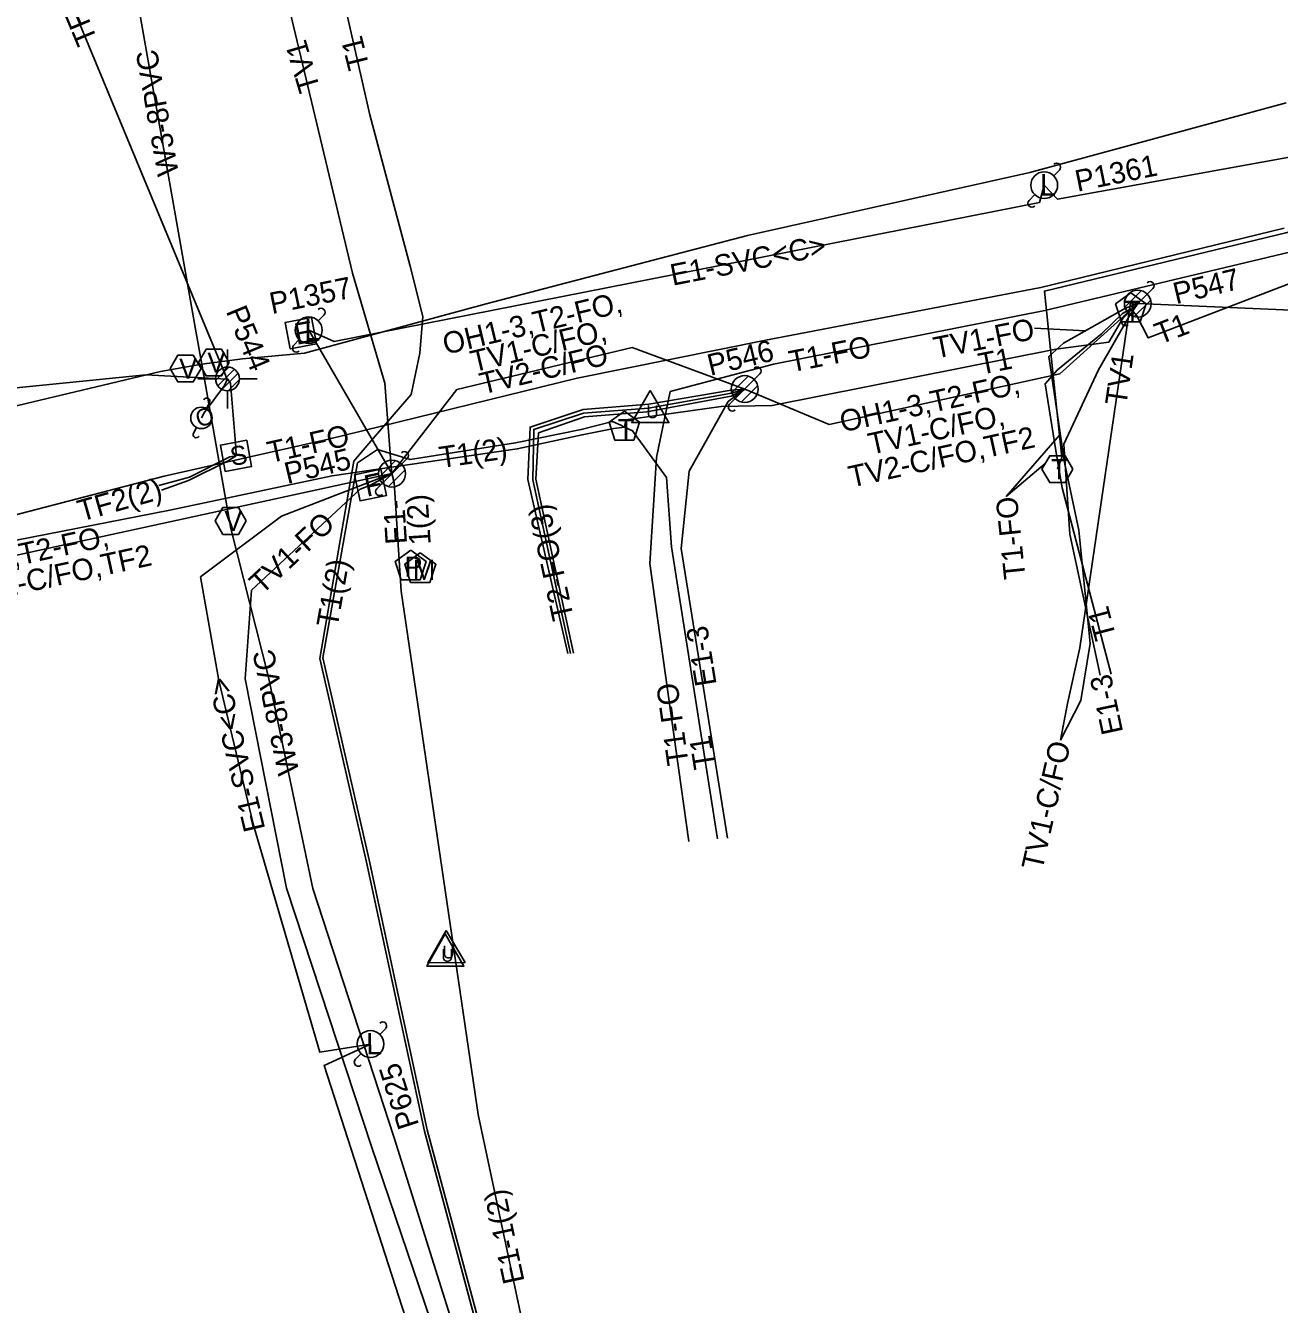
# Model space of a CAD drawing. Extents: x 2336688 to 2352634, y 362473 to 369571.
# Drawn here: x 2348017.1 to 2348250.9, y 367300.5 to 367539 of the extents above; entities that cross this region are included whole.
import ezdxf

# ---------------------------------------------------------------- set-up
doc = ezdxf.new("R2010")
doc.units = 0
for name, color, linetype in [('RD_EX_DV_Prop', 7, 'Continuous'), ('RD_EX_DV_TX_Prop', 7, 'Continuous'), ('RD_EX_RW', 7, 'Continuous'), ('RD_EX_RW_TX', 7, 'Continuous'), ('RD_HC_Data_Tic', 7, 'Continuous'), ('RD_PD_CstnLmt', 7, 'Continuous'), ('RD_PD_Final_TrvlWay', 7, 'Continuous'), ('RD_PD_FOC', 7, 'Continuous'), ('RD_PD_PatLn3', 7, 'Continuous'), ('RD_PD_PatLn4', 7, 'Continuous'), ('RD_SHT_ShtClip', 7, 'Continuous'), ('RD_Sketch2', 7, 'Continuous'), ('RD_Sketch8', 7, 'Continuous')]:
    doc.layers.add(name, color=color, linetype=linetype)

msp = doc.modelspace()

# ---------------------------------------------------------------- linework, layer by layer
at = {"layer": 'RD_EX_RW'}
for p, q in [((2348205.22, 367482.58), (2348214.7, 367482.09)), ((2348199.96, 367451.19), (2348209.88, 367462.6)), ((2348199.96, 367451.19), (2348207.23, 367457.35)), ((2348210.09, 367405.73), (2348213.89, 367413.12)), ((2348210.09, 367405.73), (2348211.36, 367412.58))]:
    msp.add_line(p, q, dxfattribs=at)
at = {"layer": 'RD_EX_RW_TX'}
for points in [[(2348085.42, 367455.46), (2348085.25, 367456.81), (2348084.11, 367472.36), (2348078.05, 367492.84), (2348059.44, 367571.03), (2348057.43, 367578.05), (2348054.24, 367593.15), (2348053.27, 367598.58), (2348079.95, 367605.18), (2348132.88, 367615.72), (2348177.98, 367626.63), (2348230.33, 367640.4), (2348274.48, 367651.48), (2348294.14, 367658.1), (2348322.12, 367668.38), (2348370.04, 367683.85), (2348388.49, 367688.84), (2348418.25, 367692.63), (2348451.32, 367697.47), (2348453.28, 367700.17), (2348444.65, 367725.62), (2348423.89, 367760.2), (2348406.22, 367798.41), (2348404.33, 367800.52)], [(2348277.67, 367644.22), (2348227.84, 367633.58), (2348178.94, 367621.43), (2348133.69, 367610.27), (2348080.57, 367598.27), (2348068.66, 367596.86), (2348066.5, 367591.91), (2348067.19, 367583.21), (2348069.73, 367573.23), (2348081.3, 367522.36), (2348088.83, 367494.16)], [(2348209.5, 367456.28), (2348210.32, 367458.48), (2348208.63, 367474.37), (2348207.08, 367489.5), (2348252.08, 367500.34), (2348310.01, 367516.64), (2348348.6, 367526.57), (2348355.1, 367525.87), (2348359.53, 367524.74)], [(2348359.53, 367524.74), (2348355.51, 367524.43), (2348310.45, 367513.44), (2348252.78, 367496.75), (2348207.14, 367485.87), (2348156.56, 367475.89), (2348137.31, 367470.75), (2348134.76, 367458.49), (2348133.52, 367438.68), (2348140.76, 367386.86)], [(2347470.17, 367338.02), (2347527.74, 367350.46), (2347547.36, 367354.41), (2347551.42, 367355.46), (2347554.94, 367356.11), (2347601.32, 367363.67), (2347672.79, 367378.26), (2347716.22, 367388.49), (2347732.21, 367393.25), (2347737, 367394.55), (2347740.32, 367395.23), (2347763.96, 367400.82), (2347812.85, 367411.94), (2347861.88, 367418.78), (2347886.02, 367419.64), (2347912.08, 367422.89), (2347964.53, 367437), (2348014.8, 367447.66), (2348042.92, 367455.01), (2348073.57, 367461.89), (2348119.92, 367473.29), (2348155.43, 367480.43), (2348206.38, 367490.17), (2348251.79, 367501.21)], [(2348088.83, 367494.16), (2348091.17, 367484.78), (2348090.64, 367477.91), (2348089.01, 367470.2), (2348081.09, 367461.1), (2348078.33, 367457.81), (2348071.94, 367420.99), (2348080.69, 367382.96), (2348091.47, 367332.8), (2348104.03, 367285.99), (2348117.2, 367236.51), (2348130.94, 367187.87), (2348140.57, 367137.57), (2348151.22, 367087.99), (2348162.48, 367041.93), (2348170.87, 366987.09)], [(2348253.93, 367491.37), (2348226.44, 367480.77), (2348224.32, 367484.9), (2348223.18, 367486.18), (2348222.03, 367484.96), (2348219.07, 367479.97), (2348209.19, 367478.65), (2348156.33, 367468.19), (2348146.8, 367468), (2348129.01, 367465.51), (2348128.75, 367464.11), (2348126.77, 367463.88), (2348120.88, 367462.71), (2348108.79, 367460.06), (2348074.24, 367455.07), (2348044, 367448.64), (2348015.43, 367443.03)], [(2348213.89, 367413.12), (2348215.59, 367423.8), (2348213.46, 367444.88), (2348210.82, 367457.54), (2348207.89, 367477.33), (2348210.65, 367479.79), (2348222.17, 367486.34), (2348224.48, 367487.16)], [(2348224.48, 367487.16), (2348223.14, 367487.36), (2348213.69, 367422.97), (2348211.36, 367412.58)], [(2348219.54, 367418.03), (2348210.35, 367452.79), (2348209.46, 367458.22), (2348207.2, 367472.18), (2348209.53, 367474.84), (2348217.73, 367481.54), (2348221.6, 367485.34), (2348223.18, 367486.18)], [(2348118.22, 367421.93), (2348110.77, 367454.36), (2348111.16, 367464.14), (2348121.09, 367467.44), (2348133.34, 367468.43), (2348148.66, 367471.02), (2348151.19, 367471.23)], [(2348118.73, 367421.93), (2348111.71, 367454.32), (2348111.86, 367463.71), (2348121.15, 367466.74), (2348133.25, 367467.67), (2348148.75, 367470.45), (2348151.19, 367471.23)], [(2348119.26, 367421.96), (2348112.25, 367454.45), (2348112.74, 367463.04), (2348121.33, 367466.07), (2348132.96, 367466.99), (2348148.69, 367469.92), (2348151.19, 367471.23)], [(2348171.52, 366987.34), (2348163.05, 367042.11), (2348151.67, 367087.97), (2348141.26, 367137.73), (2348131.53, 367187.73), (2348117.77, 367236.66), (2348104.66, 367285.95), (2348091.99, 367333.07), (2348081.16, 367383.42), (2348072.54, 367421.09), (2348078.97, 367457.45), (2348082.71, 367459.94), (2348088.78, 367458.12), (2348108.47, 367461.17), (2348120.71, 367463.68), (2348126.54, 367465.18), (2348128.12, 367464.52), (2348128.75, 367464.11), (2348130.27, 367463.44), (2348136.63, 367454.72), (2348137.56, 367441.82), (2348146.14, 367387.35)], [(2348085.42, 367455.46), (2348081.41, 367453.31), (2348079.48, 367452.55), (2348059.25, 367433.73), (2348058.03, 367417.18), (2348065.76, 367378.12), (2348081.58, 367329.95), (2348097.08, 367284.38), (2348111.65, 367235.56), (2348125.36, 367187.13), (2348134.58, 367138.22), (2348143.49, 367087.34), (2348150.94, 367037.73), (2348156.27, 366986.52)]]:
    msp.add_lwpolyline(points, dxfattribs=at)
for points in [[(2348223.18, 367489.18), (2348220.33, 367487.1), (2348221.42, 367483.75), (2348224.95, 367483.75), (2348226.04, 367487.1)], [(2348128.75, 367467.11), (2348125.9, 367465.04), (2348126.99, 367461.68), (2348130.51, 367461.68), (2348131.6, 367465.04)], [(2348212.39, 367456.28), (2348210.94, 367458.78), (2348208.06, 367458.78), (2348206.61, 367456.28), (2348208.06, 367453.78), (2348210.94, 367453.78)], [(2348083.36, 367456.26), (2348078.46, 367455.25), (2348079.47, 367450.35), (2348084.37, 367451.37)]]:
    msp.add_lwpolyline(points, close=True, dxfattribs=at)
at = {"layer": 'RD_HC_Data_Tic'}
for p, q in [((2348208.8, 367511.02), (2348209.86, 367512.09)), ((2348204.2, 367506.43), (2348205.26, 367507.49)), ((2348225.13, 367489.58), (2348222.07, 367486.52)), ((2348227.31, 367489.99), (2348226.25, 367488.93)), ((2348226.25, 367488.93), (2348222.71, 367485.4)), ((2348226.89, 367487.81), (2348223.83, 367484.75)), ((2348071.67, 367483.98), (2348072.73, 367485.04)), ((2348222.71, 367485.4), (2348221.65, 367484.34)), ((2348067.08, 367479.38), (2348068.14, 367480.45)), ((2348054.74, 367475.33), (2348054.74, 367478.62)), ((2348055.03, 367475.31), (2348052.54, 367472.82)), ((2348052.52, 367473.11), (2348049.21, 367473.11)), ((2348056.04, 367474.91), (2348052.95, 367471.81)), ((2348056.7, 367474.15), (2348053.7, 367471.15)), ((2348056.95, 367472.98), (2348054.87, 367470.9)), ((2348060.26, 367473.12), (2348056.95, 367473.12)), ((2348151.84, 367473.64), (2348148.78, 367470.58)), ((2348152.96, 367473), (2348149.42, 367469.46)), ((2348154.02, 367474.06), (2348152.96, 367473)), ((2348054.74, 367467.62), (2348054.74, 367470.9)), ((2348153.61, 367471.88), (2348150.54, 367468.81)), ((2348050.84, 367467.62), (2348051.4, 367468.68)), ((2348149.42, 367469.46), (2348148.36, 367468.4)), ((2348048.39, 367463.03), (2348048.95, 367464.09)), ((2348088.25, 367458.29), (2348087.19, 367457.23)), ((2348086.07, 367457.88), (2348083.01, 367454.81)), ((2348087.19, 367457.23), (2348083.65, 367453.69)), ((2348087.84, 367456.11), (2348084.77, 367453.05)), ((2348083.65, 367453.69), (2348082.59, 367452.63)), ((2348083.16, 367350.85), (2348084.2, 367351.92)), ((2348078.61, 367346.21), (2348079.66, 367347.28))]:
    msp.add_line(p, q, dxfattribs=at)
for centre, radius in [((2348207.03, 367509.26), 2.5), ((2348224.48, 367487.16), 2.5), ((2348069.9, 367482.21), 2.5), ((2348054.74, 367473.12), 2.22), ((2348151.19, 367471.23), 2.5), ((2348049.9, 367465.86), 2), ((2348085.42, 367455.46), 2.5), ((2348081.41, 367349.06), 2.5)]:
    msp.add_circle(centre, radius, dxfattribs=at)
for centre, radius, start, end in [((2348209.33, 367512.62), 0.75, 315, 135), ((2348204.73, 367505.9), 0.75, 135, 315), ((2348226.78, 367490.52), 0.75, 315, 135), ((2348072.2, 367485.57), 0.75, 315, 135), ((2348222.18, 367483.81), 0.75, 135, 315), ((2348067.61, 367478.85), 0.75, 135, 315), ((2348153.49, 367474.59), 0.75, 315, 135), ((2348050.87, 367468.96), 0.6, 331.9175, 151.9175), ((2348148.89, 367467.87), 0.75, 135, 315), ((2348048.92, 367462.75), 0.6, 151.9175, 331.9175), ((2348087.72, 367458.82), 0.75, 315, 135), ((2348083.12, 367452.1), 0.75, 135, 315), ((2348083.67, 367352.45), 0.75, 315.5955, 135.5955), ((2348079.14, 367345.68), 0.75, 135.5955, 315.5955)]:
    msp.add_arc(centre, radius, start, end, dxfattribs=at)
at = {"layer": 'RD_PD_Final_TrvlWay'}
for points in [[(2348085.42, 367455.46), (2348069.9, 367482.21), (2348074.61, 367480.08), (2348206.15, 367506.02), (2348207.03, 367509.26), (2348209.48, 367506.65), (2348332.4, 367528.92), (2348335.73, 367532.57)], [(2348217.45, 367417.88), (2348211.82, 367444.18), (2348210.7, 367460.98), (2348217.13, 367474.8), (2348222.98, 367485.03), (2348224.48, 367487.16)], [(2348151.19, 367471.23), (2348148.08, 367468.9), (2348140.85, 367455.9), (2348139.33, 367441.46), (2348147.98, 367387.45)], [(2348085.42, 367455.46), (2348064.82, 367447.53), (2348049.72, 367436.2), (2348053.15, 367416.84), (2348059.59, 367389.88), (2348071.96, 367347.56), (2348081.41, 367349.06), (2348072.77, 367345.05), (2348105.67, 367243.13), (2348112.74, 367243.38), (2348106.57, 367240.06), (2348121.26, 367184.97), (2348129.69, 367138.16), (2348138.15, 367139.68), (2348141, 367139.48), (2348138.4, 367138.3), (2348129.94, 367136.78), (2348147.57, 367038.81), (2348157.07, 367040.12), (2348147.81, 367036.25), (2348152.52, 366985.83)], [(2348185.82, 366991), (2348160.25, 367094.75), (2348157.29, 367121.19), (2348125.49, 367241.23), (2348111.63, 367288.28), (2348101.51, 367335.92), (2348087.12, 367433.5), (2348085.81, 367453.83), (2348085.42, 367455.46)]]:
    msp.add_lwpolyline(points, dxfattribs=at)
msp.add_lwpolyline([(2348070.44, 367484.57), (2348065.52, 367483.65), (2348066.45, 367478.73), (2348071.36, 367479.66)], close=True, dxfattribs=at)
at = {"layer": 'RD_PD_PatLn3'}
for points in [[(2348133.59, 367470.98), (2348130.13, 367464.98), (2348137.06, 367464.98)], [(2348095.52, 367370.22), (2348092.13, 367364.18), (2348099.06, 367364.27)], [(2348095.35, 367369.6), (2348091.89, 367363.6), (2348098.82, 367363.6)]]:
    msp.add_lwpolyline(points, close=True, dxfattribs=at)
at = {"layer": 'RD_SHT_ShtClip'}
for p, q in [((2348006.83, 367588.44), (2348054.67, 367473.05)), ((2347932.97, 367422.33), (2348085.42, 367455.46))]:
    msp.add_line(p, q, dxfattribs=at)
for points in [[(2348224.48, 367487.16), (2348255.92, 367485.8), (2348309.5, 367500.26), (2348335.99, 367517.26)], [(2348151.19, 367471.23), (2348166.96, 367464.65), (2348209.95, 367474.1), (2348224.48, 367487.16)], [(2348085.42, 367455.46), (2348097.52, 367471.13), (2348130.23, 367478.97), (2348151.19, 367471.23)], [(2348054.67, 367473.05), (2348039.51, 367473.91), (2347975.08, 367467.41), (2347960.39, 367463.55)]]:
    msp.add_lwpolyline(points, dxfattribs=at)
at = {"layer": 'RD_Sketch2'}
for points in [[(2348033.84, 367567.03), (2348048.77, 367482.38), (2348049.97, 367475.89), (2348055.35, 367445.23), (2348062.4, 367417.46), (2348070.65, 367378.07), (2348085.84, 367331.58), (2348100.63, 367284.45), (2348116.51, 367235.46), (2348130.22, 367187.62), (2348142.11, 367135.45), (2348149.47, 367087.77), (2348154.82, 367039.58), (2348161.67, 366987.27), (2348162.16, 366984.87)], [(2347470.35, 367337.23), (2347531.2, 367351.47), (2347577.01, 367360.75), (2347616.5, 367369.7), (2347668.2, 367379.09), (2347714.88, 367387.21), (2347764.3, 367397.77), (2347812.02, 367409.64), (2347861.32, 367422.45), (2347913.79, 367430.89), (2347937.03, 367433), (2347933.07, 367452.68), (2347964.62, 367460.29), (2348009.08, 367466.62), (2348042.26, 367474.52), (2348049.97, 367475.89), (2348057.53, 367476.89), (2348069.08, 367477.92), (2348103, 367487.1), (2348151.7, 367499.89), (2348204.32, 367511.65), (2348252.13, 367524.59)]]:
    msp.add_lwpolyline(points, dxfattribs=at)
for points in [[(2348049.82, 367475.05), (2348048.38, 367477.55), (2348045.49, 367477.55), (2348044.05, 367475.05), (2348045.49, 367472.55), (2348048.38, 367472.55)], [(2348055.09, 367476.17), (2348053.65, 367478.66), (2348050.76, 367478.66), (2348049.32, 367476.17), (2348050.76, 367473.67), (2348053.65, 367473.67)], [(2348058.24, 367446.63), (2348056.8, 367449.13), (2348053.91, 367449.13), (2348052.47, 367446.63), (2348053.91, 367444.13), (2348056.8, 367444.13)], [(2348088.91, 367441.17), (2348086.01, 367439.06), (2348087.12, 367435.65), (2348090.7, 367435.65), (2348091.81, 367439.06)], [(2348090.69, 367440.67), (2348087.79, 367438.56), (2348088.9, 367435.15), (2348092.49, 367435.15), (2348093.6, 367438.56)]]:
    msp.add_lwpolyline(points, close=True, dxfattribs=at)
at = {"layer": 'RD_Sketch8'}
for points in [[(2348049.9, 367465.86), (2348050.41, 367466.81), (2348054.2, 367471.91), (2348054.74, 367473.12)], [(2348054.74, 367473.12), (2348055.3, 367472.31), (2348056.31, 367460.4), (2348056.34, 367458.79)], [(2348041.98, 367453.22), (2348047.64, 367454.82), (2348055.2, 367458.56), (2348056.34, 367458.79)], [(2348056.34, 367458.79), (2348054.78, 367457.79), (2348047.5, 367454.19), (2348042.42, 367452.34)]]:
    msp.add_lwpolyline(points, dxfattribs=at)
msp.add_lwpolyline([(2348058.35, 367461.7), (2348053.43, 367460.79), (2348054.34, 367455.87), (2348059.25, 367456.78)], close=True, dxfattribs=at)

# ---------------------------------------------------------------- texts
at = {"layer": 'RD_EX_DV_Prop'}
for s, rotation, p in [('E1-SVC<C>', 11.1568, (2348137.74, 367490.49)), ('1(2)', 93.7056, (2348092.66, 367442.24)), ('E1-', 93.7056, (2348088.24, 367442.38)), ('E1-3', 99.1021, (2348145.97, 367416.13)), ('E1-3', 102.0765, (2348221.77, 367407.25)), ('E1-SVC<C>', 103.4379, (2348061.81, 367389.19)), ('E1-1(2)', 101.9938, (2348110.16, 367304.8))]:
    msp.add_text(s, height=4, rotation=rotation, dxfattribs=at).set_placement(p)
at = {"layer": 'RD_EX_DV_TX_Prop'}
for s, rotation, p in [('P1361', 11.5862, (2348213.24, 367508.02)), ('P1357', 11.5862, (2348063.04, 367485.2)), ('P547', 13.4802, (2348231.61, 367487.04)), ('P544', 292.5189, (2348054.41, 367485.75)), ('P546', 13.4802, (2348144.77, 367473.69)), ('P545', 13.4802, (2348065.91, 367453.49)), ('P625', 107.889, (2348090.52, 367333.97))]:
    msp.add_text(s, height=4, rotation=rotation, dxfattribs=at).set_placement(p)
at = {"layer": 'RD_EX_RW'}
for s, rotation, p in [('T1', 104.0118, (2348081.25, 367531.34)), ('TV1', 106.4656, (2348072.07, 367527.25)), ('T1', 21.0745, (2348228.59, 367479.5)), ('TV1-FO', 11.1932, (2348186.82, 367476.9)), ('T1-FO', 11.1628, (2348159.88, 367474.33)), ('T1', 11.1932, (2348195.2, 367473.89)), ('TV1', 81.6484, (2348222.31, 367467.98)), ('T1-FO', 12.6586, (2348062.69, 367457.4)), ('T1(2)', 8.2185, (2348094.52, 367456.47)), ('T2-FO(3)', 102.1868, (2348119.34, 367428.56)), ('T1-FO', 95.9501, (2348203.55, 367435.98)), ('TV1-FO', 42.9345, (2348061.15, 367432.77)), ('T1(2)', 79.9683, (2348075.25, 367426.57)), ('T1', 104.8115, (2348220.49, 367424.99)), ('T1-FO', 97.9512, (2348140.76, 367401.33)), ('T1', 98.9572, (2348145.72, 367400.67)), ('TV1-C/FO', 77.3907, (2348206.67, 367381.27))]:
    msp.add_text(s, height=4, rotation=rotation, dxfattribs=at).set_placement(p)
at = {"layer": 'RD_EX_RW_TX'}
for p in [(2348221.95, 367483.95), (2348127.52, 367461.88), (2348208.29, 367454.41)]:
    msp.add_text('T', height=3.75, dxfattribs=at).set_placement(p)
msp.add_text('F', height=4, rotation=11.6664, dxfattribs=at).set_placement((2348080.71, 367451.12))
at = {"layer": 'RD_HC_Data_Tic'}
for s, height, rotation, p in [('L', 4, 360, (2348206.22, 367507.32)), ('L', 4, 360, (2348069.09, 367480.28)), ('O', 3.2, 16.9175, (2348049.37, 367464.03)), ('L', 4, 0.5955, (2348080.62, 367347.12))]:
    msp.add_text(s, height=height, rotation=rotation, dxfattribs=at).set_placement(p)
at = {"layer": 'RD_PD_CstnLmt'}
for rotation, p in [(100.0443, (2348045.7, 367511.39)), (101.8363, (2348068.16, 367399.69))]:
    msp.add_text('W3-8PVC', height=4, rotation=rotation, dxfattribs=at).set_placement(p)
at = {"layer": 'RD_PD_Final_TrvlWay'}
msp.add_text('E', height=4, rotation=10.6261, dxfattribs=at).set_placement((2348067.62, 367479.46))
at = {"layer": 'RD_PD_FOC'}
msp.add_text('TF2(2)', height=4, rotation=15.8451, dxfattribs=at).set_placement((2348027.48, 367446.48))
at = {"layer": 'RD_PD_PatLn3'}
for p in [(2348132.84, 367465.78), (2348094.6, 367364.4)]:
    msp.add_text('U', height=2.4, dxfattribs=at).set_placement(p)
msp.add_text('U', height=2.4, rotation=0.7793, dxfattribs=at).set_placement((2348094.83, 367365.01))
at = {"layer": 'RD_PD_PatLn4'}
for s, rotation, p in [('TF2', 112.5189, (2348030.59, 367536.34)), ('OH1-3,T2-FO,', 13.4802, (2348095.42, 367477.62)), ('TV1-C/FO,', 13.4802, (2348100.61, 367474.34)), ('TV2-C/FO', 13.4802, (2348102.32, 367470.22)), ('OH1-3,T2-FO,', 12.3943, (2348169.41, 367463.14)), ('TV1-C/FO,', 12.3943, (2348174.71, 367458.97)), ('TV2-C/FO,TF2', 12.3943, (2348171.05, 367452.84)), ('OH1-3/SVC,T2-FO,', 12.2611, (2347987.3, 367432.09)), ('TV1-C/FO,TV2-C/FO,TF2', 12.2611, (2347981.09, 367425.41))]:
    msp.add_text(s, height=4, rotation=rotation, dxfattribs=at).set_placement(p)
at = {"layer": 'RD_Sketch2'}
for s, p in [('V', (2348050.99, 367474.29)), ('V', (2348045.73, 367473.17)), ('V', (2348054.15, 367444.76)), ('M', (2348089.33, 367435.63))]:
    msp.add_text(s, height=3.75, dxfattribs=at).set_placement(p)
msp.add_text('P', height=3.75, rotation=360, dxfattribs=at).set_placement((2348087.76, 367436.24))
at = {"layer": 'RD_Sketch8'}
msp.add_text('S', height=3.53, rotation=10.4256, dxfattribs=at).set_placement((2348055.6, 367456.85))

doc.saveas('drawing.dxf')
